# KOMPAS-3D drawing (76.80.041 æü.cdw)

Views: Вид 1, Вид 2
Referenced files in C:\Users\ptitsin\Desktop\Базовая грузовые\: ПТФ 436200.20.001 Плита.cdw
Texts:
  Ra 6,3
  Ra 6,3 ( )
  невидимая_RGB_0_0_0_SC_1_THICK_0.18
  GOST2.303 5_RGB_255_0_0_SC_1_THICK_0.25
  GOST2.303 6_RGB_255_0_0_SC_1_THICK_0.25
  невидимая2_RGB_0_0_0_SC_1_THICK_0.18
  невидимая2_RGB_0_0_0_SC_1_THICK_0.6
  невидимая2_RGB_255_0_0_SC_1_THICK_0.25
  POLYLINE_STYLE_0.50_RGB_0_0_0
  CONTINUOUS_RGB_255_0_0_THICK_0.25
  ACAD_ISO02W100_RGB_0_0_0_SC_0.5_THICK_0.18
  СONTINUOUS_RGB_0_0_0_THICK_0.18
  ACAD_ISO02W100_RGB_0_0_0_SC_1_THICK_0.18
  CONTINUOUS_RGB_0_0_0_THICK_0.18
  CONTINUOUS_RGB_0_0_0_THICK_0.6
  ACAD_ISO10W100_RGB_0_0_0_SC_1_THICK_0.18
  Блок ПД 476 (160т)
  Сборочный чертеж
  Т. директор
  ООО "ЗАВОД МАРКОН"
  Блок ПД 476 (160т) Сборочный чертеж
Dimensions and other numbers on the sheet: 2; 3; 5; 7; 8; 10; 11; 12; 6; 13; 15; 16; 18; 19; 20; 21; 22; 23; 24; 4; 25; 26; 27; 28; 29; 30; 1; 31; 37; 40; 45; 41; 44; 38; 1:1; 76.80.041 СБ; 76.80.041 СБ-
